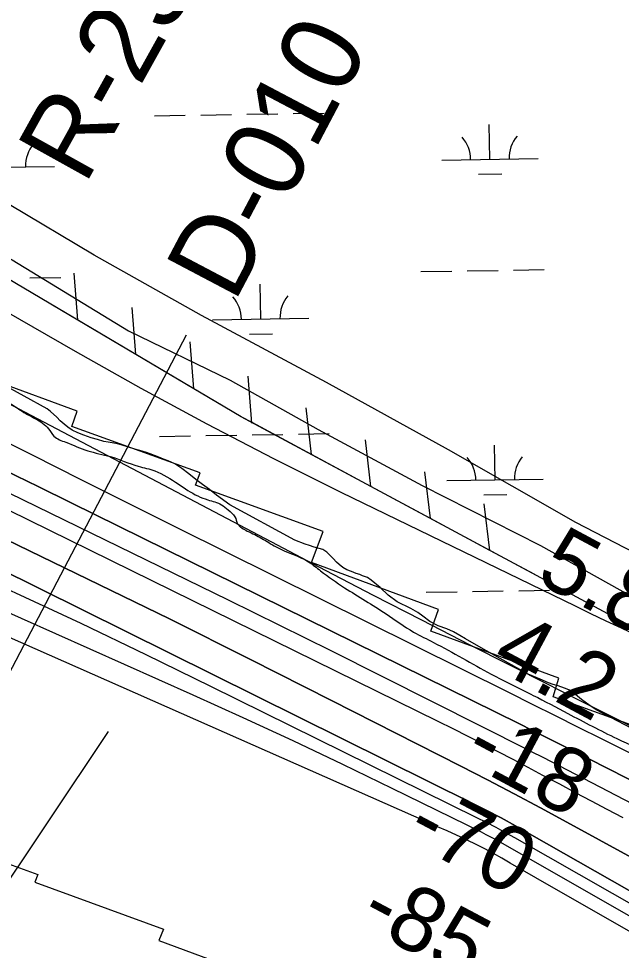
# Model space of a CAD drawing. Extents: x 3855477 to 3893699, y 299188 to 325115.
# Drawn here: x 3863042 to 3863668, y 315928 to 316895 of the extents above; entities that cross this region are included whole.
import ezdxf

# ---------------------------------------------------------------- set-up
doc = ezdxf.new("R2010")
doc.units = 0
for name, color, linetype in [('V-LEVE-TOET', 7, 'Continuous'), ('V-RIVR-EDGE', 7, 'Continuous'), ('V-RIVR-RANG', 7, 'Continuous'), ('V-RIVR-RANG-IDEN', 7, 'Continuous'), ('V-ROAD-CNTR', 7, 'Continuous'), ('V-RRAP-FSHR', 7, 'Continuous'), ('V-RRAP-RVMT', 7, 'Continuous'), ('V-TOPO-DPTH', 7, 'Continuous'), ('V-TOPO-MAJR', 7, 'Continuous'), ('V-TOPO-MINR', 7, 'Continuous'), ('V-TOPO-WATR', 7, 'Continuous'), ('V-WETL-SWMP', 7, 'Continuous')]:
    doc.layers.add(name, color=color, linetype=linetype)

msp = doc.modelspace()

# ---------------------------------------------------------------- linework, layer by layer
at = {"layer": 'V-LEVE-TOET'}
for points in [[(3864365.02, 315977.84), (3864291.52, 316022.98), (3864202.21, 316071.98), (3864114.46, 316118.32), (3864011.47, 316172.75), (3863900.03, 316227.26), (3863792.82, 316282.79), (3863620.45, 316372.27), (3863488.09, 316447.6), (3863361.48, 316517.59), (3863231.7, 316587.09), (3863120.34, 316649.52), (3863032.12, 316702.21), (3862931.78, 316757.14), (3862812.04, 316826.53), (3862709.02, 316878.84), (3862581.85, 316945.14), (3862463.67, 317012.4), (3862350.14, 317069.05)], [(3862570.28, 316898.77), (3862675.32, 316837.98), (3862776.17, 316780.94), (3862848.7, 316744.26), (3862938.05, 316698.96), (3863035.23, 316644.59), (3863155.98, 316570.97), (3863261.65, 316519.68), (3863353.05, 316468.55), (3863460.76, 316410.37), (3863583.75, 316348.35), (3863677.77, 316295.6), (3863771.86, 316248.66), (3863851.78, 316211.38), (3863907.02, 316188.09), (3864001.5, 316127.94), (3864120.16, 316055.92), (3864180.06, 316024.66), (3864287.88, 315977.05), (3864332.62, 315960.74), (3864357.98, 315960.48), (3864374.39, 315963.48), (3864374.47, 315971.4), (3864365.02, 315977.84)]]:
    msp.add_lwpolyline(points, dxfattribs=at)
at = {"layer": 'V-RIVR-EDGE'}
msp.add_spline([(3862579.14, 316706.58), (3862618.94, 316682.57), (3862652.77, 316666.14), (3862683.04, 316656.5), (3862696.18, 316652.88), (3862701.35, 316646.89), (3862715.28, 316640.08), (3862730.01, 316634.47), (3862738.78, 316633.65), (3862748.32, 316626.05), (3862763.45, 316620.43), (3862771.01, 316614.84), (3862792.51, 316606.02), (3862806.84, 316598.81), (3862817.99, 316594.4), (3862834.31, 316586.78), (3862853.02, 316578.37), (3862861.77, 316570.77), (3862880.08, 316564.75), (3862890.05, 316564.73), (3862900.01, 316564.3), (3862907.58, 316561.49), (3862923.9, 316554.68), (3862944.6, 316544.66), (3862975.64, 316529.04), (3863008.68, 316511.03), (3863036.93, 316493.42), (3863051.26, 316484.22), (3863059.61, 316479.82), (3863073.14, 316469.42), (3863078.7, 316461.84), (3863091.04, 316455.43), (3863113.73, 316446.6), (3863137.23, 316440.57), (3863166.3, 316430.53), (3863183.42, 316425.71), (3863207.7, 316412.1), (3863228, 316399.69), (3863238.35, 316395.68), (3863252.68, 316390.47), (3863259.44, 316385.27), (3863266.6, 316378.08), (3863269.37, 316370.9), (3863279.32, 316363.3), (3863294.44, 316355.69), (3863309.17, 316346.89), (3863343, 316331.26), (3863355.34, 316322.06), (3863380.4, 316304.47), (3863423.37, 316277.26), (3863452.02, 316258.46), (3863472.72, 316247.65), (3863532.42, 316214.82), (3863576.2, 316192.79), (3863612.02, 316173.97), (3863662.97, 316147.94), (3863701.98, 316129.91), (3863762.09, 316101.46), (3863803.49, 316080.64), (3863847.67, 316056.62), (3863876.33, 316044.19), (3863896.63, 316031.79), (3863917.72, 316020.58), (3863971.85, 315991.35), (3864020.81, 315966.12), (3864054.23, 315946.51), (3864091.65, 315926.89), (3864114.73, 315913.68), (3864131.85, 315906.86), (3864146.97, 315897.66), (3864174.04, 315883.64), (3864183.18, 315874.06), (3864194.33, 315870.44), (3864207.47, 315866.82), (3864224.19, 315858.81), (3864239.32, 315850.4), (3864262.4, 315839.98), (3864273.56, 315837.17), (3864288.68, 315830.35), (3864303.82, 315827.93), (3864315.37, 315825.11), (3864338.47, 315817.08), (3864360.77, 315810.65), (3864391.41, 315792.24), (3864418.87, 315776.23), (3864435.97, 315762.24), (3864459.04, 315741.86), (3864510.37, 315709.85), (3864535.44, 315695.84), (3864548.97, 315685.44), (3864561.3, 315675.85), (3864568.85, 315666.66), (3864582.37, 315656.66), (3864595.1, 315647.07), (3864600.67, 315641.08), (3864607.02, 315633.09), (3864612.59, 315626.3), (3864620.15, 315622.69), (3864637.27, 315615.88), (3864659.57, 315609.05), (3864678.28, 315601.03), (3864697.4, 315595.4), (3864745.56, 315571.77), (3864769.85, 315563.74), (3864787.37, 315555.73), (3864811.24, 315540.52), (3864821.2, 315537.71), (3864833.16, 315537.68), (3864842.32, 315536.46), (3864849.48, 315531.26), (3864857.43, 315522.87), (3864872.16, 315516.86), (3864908, 315506.01), (3864925.13, 315500.39), (3864937.87, 315498.76), (3864948.62, 315491.56), (3864956.98, 315489.55), (3864964.15, 315487.54), (3865017.51, 315468.28), (3865068.47, 315449.82), (3865096.34, 315439.39), (3865128.59, 315424.96), (3865154.87, 315414.93), (3865175.96, 315401.73), (3865212.19, 315385.7), (3865243.63, 315368.48), (3865263.13, 315356.48), (3865277.85, 315348.07), (3865296.96, 315338.06), (3865316.47, 315331.24), (3865337.16, 315318.04), (3865369.39, 315298.43), (3865405.2, 315275.22), (3865431.87, 315259.61), (3865448.19, 315254), (3865473.66, 315238.39), (3865499.13, 315224.78), (3865515.06, 315217.96), (3865531.77, 315209.15), (3865549.68, 315199.54), (3865571.18, 315191.52), (3865609, 315173.09), (3865653.97, 315145.48), (3865693.76, 315123.07), (3865732.77, 315101.85), (3865776.94, 315077.43), (3865798.43, 315063.82), (3865826.69, 315046.62), (3865853.35, 315032.6), (3865883.2, 315017.39), (3865895.15, 315011.38), (3865904.29, 315003.78), (3865913.04, 314994.59), (3865919.8, 314990.19), (3865927.77, 314987.38), (3865939.71, 314983.37), (3865950.47, 314980.55), (3865961.62, 314976.54), (3865977.53, 314967.34), (3866028.88, 314942.9), (3866056.75, 314928.48), (3866076.64, 314915.28), (3866096.53, 314901.68), (3866120.41, 314888.47), (3866143.9, 314878.05), (3866161.41, 314867.25), (3866178.14, 314862.82), (3866201.24, 314856.79), (3866223.14, 314850.36), (3866245.83, 314837.55), (3866263.73, 314827.14), (3866282.84, 314818.72), (3866292.41, 314818.7), (3866300.78, 314818.28), (3866309.94, 314816.27), (3866326.66, 314808.65), (3866348.53, 314791.06), (3866360.08, 314786.25), (3866377.59, 314778.64), (3866387.55, 314775.02), (3866394.31, 314767.44), (3866401.87, 314762.24), (3866413.81, 314757.03), (3866423.36, 314751.42), (3866432.12, 314749.81), (3866437.69, 314746.21), (3866445.65, 314739.41), (3866454.4, 314732.22), (3866485.45, 314718.99), (3866510.53, 314708.56), (3866533.21, 314691.37), (3866541.97, 314691.35), (3866549.94, 314690.93), (3866556.31, 314686.53), (3866561.87, 314678.55), (3866573.8, 314670.15), (3866598.9, 314663.71), (3866631.14, 314649.28), (3866660.61, 314640.44), (3866694.86, 314628.4), (3866748.2, 314604.36), (3866780.45, 314591.52), (3866811.1, 314575.51), (3866846.93, 314561.47), (3866895.5, 314539.03), (3866932.13, 314524.59), (3866954.81, 314513.38), (3866988.26, 314500.54), (3867018.51, 314486.52), (3867041.2, 314475.3), (3867068.66, 314458.5), (3867097.31, 314440.09), (3867123.99, 314432.46), (3867147.11, 314433.2), (3867169.41, 314427.96), (3867197.28, 314417.13), (3867215.2, 314410.71), (3867238.69, 314401.49), (3867251.43, 314396.27), (3867258.61, 314395.86), (3867271.36, 314397.42), (3867288.1, 314397.78), (3867302.45, 314396.15), (3867345.46, 314385.28), (3867427.5, 314359.57), (3867438.25, 314357.95), (3867445.03, 314357.93), (3867453.42, 314369.47), (3867458.24, 314381.41), (3867462.26, 314395.75), (3867462.28, 314404.12), (3867460.7, 314411.7), (3867457.12, 314414.1), (3867450.75, 314416.11), (3867442.78, 314416.52), (3867438.8, 314420.12), (3867443.19, 314422.1), (3867451.58, 314428.06), (3867458.77, 314437.21), (3867459.58, 314442.79), (3867460, 314450.75), (3867463.6, 314455.13), (3867470.8, 314463.88), (3867472, 314469.46), (3867472.42, 314477.03), (3867471.64, 314485), (3867465.71, 314504.54), (3867463.75, 314514.51), (3867463.37, 314524.48), (3867464.21, 314541.21), (3867469.07, 314571.09), (3867474.67, 314579.84), (3867478.26, 314581.43), (3867485.04, 314582.61), (3867525.27, 314574.94), (3867536.02, 314568.93), (3867545.17, 314565.72), (3867555.14, 314566.49), (3867569.88, 314566.06), (3867581.03, 314559.65), (3867584.99, 314552.07), (3867591.75, 314543.69), (3867611.65, 314532.88), (3867627.95, 314518.09), (3867650.21, 314493.33), (3867659.75, 314484.93), (3867663.31, 314472.97), (3867663.27, 314455.43), (3867660.06, 314447.47), (3867647.3, 314446.31), (3867632.15, 314444.75), (3867612.61, 314438.42), (3867582.29, 314425.34)], degree=3, dxfattribs=at)
at = {"layer": 'V-RIVR-RANG'}
msp.add_line((3863215.95, 316566.62), (3862844.67, 315858), dxfattribs=at)
at = {"layer": 'V-ROAD-CNTR'}
msp.add_lwpolyline([(3860065.6, 311560.18), (3863135.44, 316155.31)], dxfattribs=at)
at = {"layer": 'V-RRAP-FSHR'}
for p, q in [((3863103.39, 316582.2), (3863099.65, 316630.89)), ((3863163.64, 316546.56), (3863159.9, 316595.25)), ((3863223.89, 316510.92), (3863220.15, 316559.61)), ((3863284.13, 316475.29), (3863280.39, 316523.97)), ((3863346.06, 316442.61), (3863340.32, 316491.11)), ((3863407.71, 316409.47), (3863401.98, 316457.97)), ((3863469.37, 316376.33), (3863463.64, 316424.82)), ((3863531.02, 316343.19), (3863525.29, 316391.68))]:
    msp.add_line(p, q, dxfattribs=at)
for points in [[(3863755.9, 316222.32), (3863272.86, 316481.96), (3862847.86, 316733.36), (3862473.5, 316926.11), (3861935.6, 317229.54), (3861789.61, 317312.68)], [(3863103.39, 316582.2), (3863077.15, 316597.72)], [(3863163.64, 316546.56), (3863103.39, 316582.2)], [(3863223.89, 316510.92), (3863163.64, 316546.56)], [(3863284.4, 316475.75), (3863272.86, 316481.96), (3863223.89, 316510.92)], [(3863346.06, 316442.61), (3863284.4, 316475.75)], [(3863407.71, 316409.47), (3863346.05, 316442.61)], [(3863469.37, 316376.33), (3863407.71, 316409.47)], [(3863577.59, 316318.16), (3863531.02, 316343.19), (3863469.37, 316376.33)]]:
    msp.add_lwpolyline(points, dxfattribs=at)
at = {"layer": 'V-RRAP-RVMT'}
for p, q in [((3863102.97, 316487.8), (3862969.59, 316536.63)), ((3863097.28, 316471.87), (3863102.97, 316487.8)), ((3863230.37, 316423.75), (3863097.28, 316471.87)), ((3863225.72, 316410.88), (3863230.37, 316423.75)), ((3863358.2, 316362.74), (3863225.72, 316410.88)), ((3863346.08, 316330.55), (3863358.2, 316362.74)), ((3863477.95, 316281.96), (3863346.08, 316330.55)), ((3863469.78, 316259.28), (3863477.95, 316281.96)), ((3863602.81, 316210.69), (3863469.78, 316259.28)), ((3863596.71, 316191.35), (3863602.81, 316210.69)), ((3863728.29, 316143.47), (3863596.71, 316191.35)), ((3862929.29, 316055.02), (3863061.95, 316006.79)), ((3863061.95, 316006.79), (3863059.01, 315998.92)), ((3863059.01, 315998.92), (3863192.36, 315950.29)), ((3863192.36, 315950.29), (3863187.69, 315938.41)), ((3863187.69, 315938.41), (3863319.55, 315889.88))]:
    msp.add_line(p, q, dxfattribs=at)
at = {"layer": 'V-TOPO-DPTH'}
for points in [[(3863687.1, 316156.12), (3863630.2, 316184.48), (3863620.72, 316189.22), (3863611.25, 316193.97), (3863601.79, 316198.74), (3863592.34, 316203.54), (3863510.78, 316245.01), (3863460.61, 316270.66), (3863410.5, 316296.44), (3863360.51, 316322.43), (3863310.58, 316348.55), (3862976.42, 316524.28), (3862950.08, 316537.92), (3862923.64, 316551.34), (3862897.03, 316564.42), (3862870.31, 316577.29), (3862710.79, 316652.88), (3862647.57, 316681.17), (3862583.62, 316707.59), (3862518.57, 316731.19), (3862452.8, 316752.91), (3862359.91, 316781.36)], [(3862347.54, 316746.73), (3862400.7, 316719.9), (3862454.28, 316693.92), (3862508.14, 316668.51), (3862821.29, 316523.8), (3862855.89, 316507.75), (3862890.45, 316491.62), (3862924.97, 316475.38), (3862959.44, 316459.06), (3862993.86, 316442.62), (3863028.22, 316426.07), (3863062.51, 316409.37), (3863096.76, 316392.57), (3863561.69, 316163.12), (3863574.79, 316156.63), (3863587.87, 316150.1), (3863600.93, 316143.53), (3863613.97, 316136.92), (3863986.61, 315947.23)], [(3862347.54, 316746.73), (3862400.7, 316719.9), (3862454.28, 316693.92), (3862508.14, 316668.51), (3862821.29, 316523.8), (3862855.89, 316507.75), (3862890.45, 316491.62), (3862924.97, 316475.38), (3862959.44, 316459.06), (3862993.86, 316442.62), (3863028.22, 316426.07), (3863062.51, 316409.37), (3863096.76, 316392.57), (3863561.69, 316163.12), (3863574.79, 316156.63), (3863587.87, 316150.1), (3863600.93, 316143.53), (3863613.97, 316136.92), (3863986.61, 315947.23)], [(3862339.28, 316674.71), (3862633.23, 316541.24), (3862671.07, 316523.97), (3862708.87, 316506.6), (3862746.6, 316489.08), (3862784.29, 316471.47), (3862835.29, 316447.51), (3862847.43, 316441.79), (3862859.57, 316436.04), (3862871.68, 316430.26), (3862883.79, 316424.46), (3863029.31, 316354.54), (3863114.03, 316313.48), (3863198.56, 316272.03), (3863282.8, 316230.01), (3863366.86, 316187.61), (3863500.88, 316119.43), (3863528.6, 316105.17), (3863556.23, 316090.73), (3863583.72, 316076.04), (3863611.12, 316061.17), (3863748.82, 315985.63)], [(3863748.82, 315985.63), (3863611.12, 316061.17), (3863583.72, 316076.04), (3863556.23, 316090.73), (3863528.6, 316105.17), (3863500.88, 316119.43), (3863366.86, 316187.61), (3863282.8, 316230.01), (3863198.56, 316272.03), (3863114.03, 316313.48), (3863029.31, 316354.54), (3862883.79, 316424.46), (3862871.68, 316430.26), (3862859.57, 316436.04), (3862847.43, 316441.79), (3862835.29, 316447.51), (3862784.29, 316471.47), (3862746.6, 316489.08), (3862708.87, 316506.6), (3862671.07, 316523.97), (3862633.23, 316541.24), (3862339.28, 316674.71)], [(3862340.76, 316647), (3862381.53, 316627.91), (3862843.66, 316411.69), (3862844.6, 316411.25), (3862847.43, 316409.94), (3862858.49, 316404.83), (3862864.96, 316401.81), (3862871.4, 316398.76), (3862877.82, 316395.65), (3862884.22, 316392.51), (3863512.75, 316080.95), (3863527.82, 316073.32), (3863542.79, 316065.53), (3863557.63, 316057.47), (3863572.38, 316049.25), (3864306.62, 315631.55)], [(3864306.62, 315631.55), (3863572.38, 316049.25), (3863557.63, 316057.47), (3863542.79, 316065.53), (3863527.82, 316073.32), (3863512.75, 316080.95), (3862884.22, 316392.51), (3862877.82, 316395.65), (3862871.4, 316398.76), (3862864.96, 316401.81), (3862858.49, 316404.83), (3862847.43, 316409.94), (3862844.6, 316411.25), (3862843.66, 316411.69), (3862381.53, 316627.91), (3862340.76, 316647)], [(3863669.45, 316065.68), (3863652.96, 316074.33), (3863636.49, 316083), (3863620.04, 316091.72), (3863603.61, 316100.48), (3863601.62, 316101.54), (3863586.19, 316109.76), (3863570.73, 316117.95), (3863555.25, 316126.08), (3863539.75, 316134.17), (3863524.21, 316142.18), (3863508.63, 316150.13), (3863493, 316157.96), (3863477.33, 316165.73), (3862925, 316437.18)], [(3863669.45, 316065.68), (3863652.96, 316074.33), (3863636.49, 316083), (3863620.04, 316091.72), (3863603.61, 316100.48), (3863601.62, 316101.54), (3863586.19, 316109.76), (3863570.73, 316117.95), (3863555.25, 316126.08), (3863539.75, 316134.17), (3863524.21, 316142.18), (3863508.63, 316150.13), (3863493, 316157.96), (3863477.33, 316165.73), (3862925, 316437.18)]]:
    msp.add_lwpolyline(points, dxfattribs=at)
at = {"layer": 'V-TOPO-MAJR'}
msp.add_lwpolyline([(3863893.33, 315853.22), (3863557.11, 316044.81), (3863547.33, 316050.26), (3863537.5, 316055.6), (3863527.58, 316060.76), (3863517.59, 316065.8), (3863241.6, 316202.07), (3863174.37, 316234.84), (3863106.94, 316267.17), (3863039.19, 316298.83), (3862971.23, 316330.04), (3862856.68, 316381.97), (3862845.84, 316386.9), (3862835.01, 316391.85), (3862824.19, 316396.82), (3862813.38, 316401.81), (3862567.32, 316515.77), (3862493.51, 316550.04), (3862419.74, 316584.41), (3862346.04, 316618.92)], dxfattribs=at)
at = {"layer": 'V-TOPO-MINR'}
for points in [[(3863986.61, 315947.23), (3863613.97, 316136.92), (3863600.93, 316143.53), (3863587.87, 316150.1), (3863574.79, 316156.63), (3863561.69, 316163.12), (3863096.76, 316392.57), (3863062.51, 316409.37), (3863028.22, 316426.07), (3862993.86, 316442.62), (3862959.44, 316459.06), (3862924.97, 316475.38), (3862890.45, 316491.62), (3862855.89, 316507.75), (3862821.29, 316523.8), (3862508.14, 316668.51), (3862454.28, 316693.92), (3862400.7, 316719.9), (3862347.54, 316746.73)], [(3864294.09, 315759.78), (3863586.33, 316128.15), (3863582.35, 316130.21), (3863578.36, 316132.26), (3863574.37, 316134.3), (3863570.38, 316136.33), (3863472.39, 316185.8), (3863419.35, 316212.45), (3863366.24, 316238.95), (3863313.02, 316265.24), (3863259.73, 316291.4), (3862946.85, 316444.17), (3862914.25, 316459.98), (3862881.61, 316475.7), (3862848.89, 316491.25), (3862816.13, 316506.7), (3862628.22, 316594.74), (3862553.23, 316630.53), (3862478.59, 316667.03), (3862404.48, 316704.59), (3862330.72, 316742.86)], [(3863714.8, 315941.65), (3863653.97, 315976.39), (3863541.84, 316040.39), (3863537.04, 316043.07), (3863532.22, 316045.69), (3863527.34, 316048.21), (3863522.44, 316050.68), (3863429.88, 316096.21), (3863378.54, 316121.11), (3863327.02, 316145.62), (3863275.22, 316169.55), (3863223.24, 316193.1), (3862866.71, 316352.19), (3862845.2, 316361.83), (3862823.71, 316371.52), (3862802.25, 316381.29), (3862780.81, 316391.1), (3862681.74, 316436.65), (3862610.84, 316469.38), (3862539.99, 316502.24), (3862469.25, 316535.32), (3862398.57, 316568.53), (3862135.83, 316692.45)], [(3863748.82, 315985.63), (3863611.12, 316061.17), (3863583.72, 316076.04), (3863556.23, 316090.73), (3863528.6, 316105.17), (3863500.88, 316119.43), (3863366.86, 316187.61), (3863282.8, 316230.01), (3863198.56, 316272.03), (3863114.03, 316313.48), (3863029.31, 316354.54), (3862883.79, 316424.46), (3862871.68, 316430.26), (3862859.57, 316436.04), (3862847.43, 316441.79), (3862835.29, 316447.51), (3862784.29, 316471.47), (3862746.6, 316489.08), (3862708.87, 316506.6), (3862671.07, 316523.97), (3862633.23, 316541.24), (3862339.28, 316674.71)], [(3864412.89, 315889.33), (3863957.17, 316123.81), (3863906.82, 316149.3), (3863856.24, 316174.33), (3863805.33, 316198.69), (3863754.21, 316222.59), (3863683.71, 316254.98), (3863667.69, 316262.4), (3863651.71, 316269.9), (3863635.77, 316277.49), (3863619.87, 316285.16), (3863376.75, 316403.41), (3863306.95, 316438.26), (3863237.66, 316474.06), (3863169.13, 316511.3), (3863101.1, 316549.49), (3863012.98, 316600.17), (3862989.52, 316613.95), (3862966.24, 316628.01), (3862943.23, 316642.49), (3862920.38, 316657.26)], [(3864306.62, 315631.55), (3863572.38, 316049.25), (3863557.63, 316057.47), (3863542.79, 316065.53), (3863527.82, 316073.32), (3863512.75, 316080.95), (3862884.22, 316392.51), (3862877.82, 316395.65), (3862871.4, 316398.76), (3862864.96, 316401.81), (3862858.49, 316404.83), (3862847.43, 316409.94), (3862844.6, 316411.25), (3862843.66, 316411.69), (3862381.53, 316627.91), (3862340.76, 316647)], [(3863770.12, 316085.69), (3863647, 316147.54), (3863623.13, 316159.51), (3863599.25, 316171.46), (3863575.36, 316183.38), (3863551.46, 316195.27), (3863208.03, 316365.94), (3863157.47, 316391.15), (3863106.97, 316416.45), (3863056.53, 316441.88), (3863006.14, 316467.41)], [(3863669.45, 316065.68), (3863652.96, 316074.33), (3863636.49, 316083), (3863620.04, 316091.72), (3863603.61, 316100.48), (3863601.62, 316101.54), (3863586.19, 316109.76), (3863570.73, 316117.95), (3863555.25, 316126.08), (3863539.75, 316134.17), (3863524.21, 316142.18), (3863508.63, 316150.13), (3863493, 316157.96), (3863477.33, 316165.73), (3862925, 316437.18)], [(3864293.81, 315594.56), (3863578.67, 316003.48), (3863569.87, 316008.53), (3863561.08, 316013.6), (3863552.3, 316018.7), (3863543.54, 316023.81), (3863534.72, 316028.81), (3863525.8, 316033.63), (3863516.74, 316038.18), (3863507.59, 316042.56), (3863506.38, 316043.11), (3863496.55, 316047.61), (3863486.7, 316052.08), (3863476.83, 316056.5), (3863466.95, 316060.89), (3862877.26, 316321.18)]]:
    msp.add_lwpolyline(points, dxfattribs=at)
at = {"layer": 'V-TOPO-WATR'}
msp.add_lwpolyline([(3863687.1, 316156.12), (3863630.2, 316184.48), (3863620.72, 316189.22), (3863611.25, 316193.97), (3863601.79, 316198.74), (3863592.34, 316203.54), (3863510.78, 316245.01), (3863460.61, 316270.66), (3863410.5, 316296.44), (3863360.51, 316322.43), (3863310.58, 316348.55), (3862976.42, 316524.28), (3862950.08, 316537.92), (3862923.64, 316551.34), (3862897.03, 316564.42), (3862870.31, 316577.29), (3862710.79, 316652.88), (3862647.57, 316681.17), (3862583.62, 316707.59), (3862518.57, 316731.19), (3862452.8, 316752.91), (3862359.91, 316781.36)], dxfattribs=at)
at = {"layer": 'V-WETL-SWMP'}
for p, q in [((3863231.01, 316794.94), (3863263, 316795.46)), ((3863279, 316795.72), (3863311, 316796.24)), ((3863327, 316796.5), (3863358.99, 316797.02)), ((3863183.01, 316794.16), (3863215.01, 316794.68)), ((3863531.11, 316749.08), (3863530.52, 316785.07)), ((3863481.12, 316748.27), (3863581.1, 316749.89)), ((3862979.28, 316740.09), (3863079.26, 316741.72)), ((3863519.36, 316733.46), (3863543.36, 316733.85)), ((3863459.59, 316632.47), (3863491.59, 316632.99)), ((3863507.59, 316633.25), (3863539.58, 316633.77)), ((3863555.58, 316634.03), (3863587.58, 316634.55)), ((3863053.74, 316625.86), (3863085.73, 316626.38)), ((3863293.31, 316583.32), (3863292.72, 316619.32)), ((3863243.31, 316582.51), (3863343.3, 316584.14)), ((3863281.56, 316567.7), (3863305.56, 316568.09)), ((3863188.43, 316461.53), (3863220.43, 316462.05)), ((3863236.43, 316462.31), (3863268.42, 316462.83)), ((3863284.42, 316463.09), (3863316.42, 316463.61)), ((3863332.41, 316463.87), (3863364.41, 316464.39)), ((3863536.53, 316416.45), (3863535.94, 316452.44)), ((3863486.54, 316415.63), (3863586.52, 316417.26)), ((3863524.78, 316400.82), (3863548.78, 316401.22)), ((3863561, 316301.4), (3863593, 316301.92)), ((3863465.01, 316299.84), (3863497.01, 316300.36)), ((3863513.01, 316300.62), (3863545, 316301.14))]:
    msp.add_line(p, q, dxfattribs=at)
for points in [[(3863596.93, 316204.12), (3863591.77, 316205.9), (3863583.36, 316209.63), (3863570.94, 316214.75), (3863524.57, 316240.75), (3863505.68, 316251.31), (3863499.76, 316255.02), (3863493.47, 316258.73), (3863486.59, 316261.68), (3863477.6, 316265.04), (3863468.82, 316269.35), (3863461.39, 316274.8), (3863456.25, 316278.89), (3863449, 316282.8), (3863435.06, 316289.66), (3863425.73, 316296.86), (3863417.17, 316304.62), (3863407.85, 316312.4), (3863404.23, 316314.93), (3863399.06, 316316.9), (3863396, 316318.09), (3863392.18, 316319.28), (3863387.59, 316321.24), (3863382.62, 316323.02), (3863378.62, 316325.37), (3863374.62, 316328.67), (3863371.96, 316331), (3863368.54, 316334.68), (3863365.12, 316338.36), (3863361.89, 316341.28), (3863357.89, 316344.01), (3863348.89, 316346.4), (3863343.92, 316348.18), (3863339.33, 316349.76), (3863328.62, 316353.71), (3863261.25, 316390.49), (3863247.35, 316400.61), (3863240.3, 316406.44), (3863232.87, 316411.51), (3863226.02, 316416.76), (3863218.79, 316422.79), (3863211.55, 316428.04), (3863204.31, 316433.11), (3863197.24, 316436.25), (3863192.26, 316437.84), (3863187.68, 316439.81), (3863178.69, 316443.55), (3863174.68, 316444.93), (3863167.79, 316446.92), (3863162.81, 316448.32), (3863156.12, 316450.31), (3863149.42, 316452.29), (3863144.64, 316453.69), (3863139.08, 316454.9), (3863135.06, 316455.51), (3863130.46, 316456.33), (3863123.76, 316458.32), (3863117.45, 316460.11), (3863109.61, 316462.88), (3863103.68, 316465.05), (3863097.76, 316467.8), (3863093, 316471.11), (3863089.19, 316474.22), (3863085.19, 316477.72), (3863081.59, 316481.4), (3863075.31, 316487.22), (3863071.7, 316490.14), (3863023.99, 316516.54)], [(3863679.17, 316157.97), (3863641.57, 316177.74), (3863633.94, 316182.81), (3863626.32, 316188.46), (3863620.04, 316193.51), (3863612.99, 316198.38), (3863608.4, 316200.16), (3863601.9, 316202.53), (3863596.93, 316204.12)]]:
    msp.add_lwpolyline(points, dxfattribs=at)
for centre, start, end in [((3863475.87, 316748.65), 0.16154, 41.7052), ((3863586.34, 316750.45), 140.16154, 181.7052), ((3863084.5, 316742.28), 140.16154, 181.7052), ((3863238.06, 316582.9), 0.16154, 41.7052), ((3863348.54, 316584.7), 140.16154, 181.7052), ((3863481.29, 316416.02), 0.16154, 41.7052), ((3863591.76, 316417.82), 140.16154, 181.7052)]:
    msp.add_arc(centre, 35.25, start, end, dxfattribs=at)

# ---------------------------------------------------------------- texts
at = {"layer": 'V-RIVR-RANG'}
for s, rotation, p in [('5.8', 331.79833, (3863577.08, 316311.75)), ('4.2', 331.79833, (3863530.04, 316223.5)), ('-18', 331.79833, (3863500.91, 316125.65)), ('-70', 332.08478, (3863441.05, 316043.83)), ('-85', 332.08478, (3863392.85, 315956.2))]:
    msp.add_text(s, height=67, rotation=rotation, dxfattribs=at).set_placement(p)
at = {"layer": 'V-RIVR-RANG-IDEN'}
for s, rotation, p in [('R-23.7', 60.94865, (3863110.79, 316721.12)), ('D-010', 62.20633, (3863265.73, 316598.88))]:
    msp.add_text(s, height=83, rotation=rotation, dxfattribs=at).set_placement(p)

doc.saveas('drawing.dxf')
